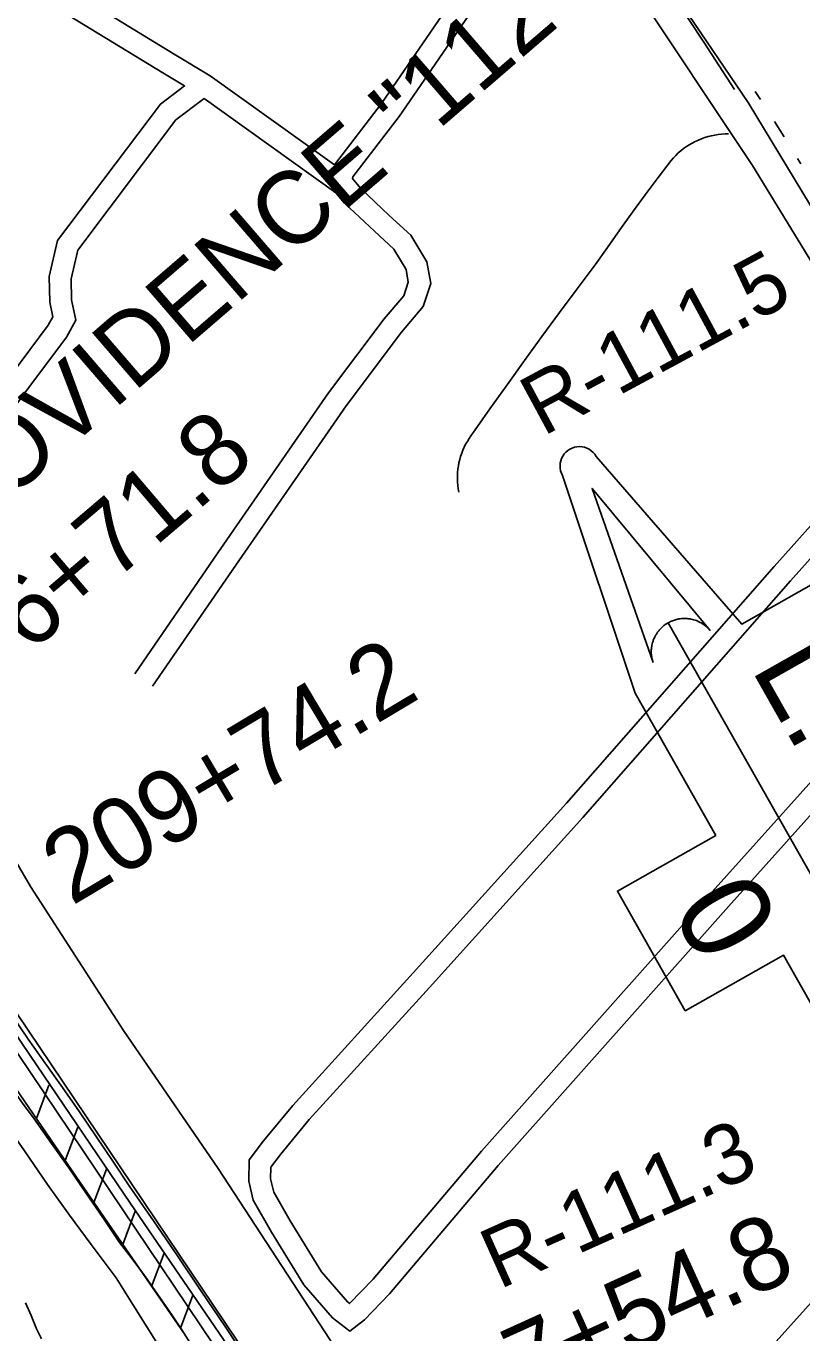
# Model space of a CAD drawing. Extents: x 3625074 to 3663148, y 511451 to 537151.
# Drawn here: x 3632681 to 3633748, y 530470 to 532267 of the extents above; entities that cross this region are included whole.
import ezdxf

# ---------------------------------------------------------------- set-up
doc = ezdxf.new("R2010")
doc.units = 0
for name, color, linetype in [('V-CHAN-NAID', 7, 'Continuous'), ('V-FLOD-BASE', 7, 'Continuous'), ('V-LEVE-TOET', 7, 'Continuous'), ('V-RIVR-RANG-IDEN', 7, 'Continuous'), ('V-ROAD-CNTR', 7, 'Continuous'), ('V-RRAP-FSHR', 7, 'Continuous'), ('V-SITE-VEGE', 7, 'Continuous'), ('V-SURV-IDEN', 7, 'Continuous'), ('V-SURV-LINE', 7, 'Continuous'), ('V-TOPO-SHOR', 7, 'Continuous'), ('V-TOPO-WATR-IDEN', 7, 'Continuous')]:
    doc.layers.add(name, color=color, linetype=linetype)

msp = doc.modelspace()

# ---------------------------------------------------------------- linework, layer by layer
at = {"layer": 'V-FLOD-BASE'}
msp.add_lwpolyline([(3632971.5, 530433.4), (3632824.8, 530647.7), (3632686.6, 530851.6), (3632644.4, 530913.1)], dxfattribs=at)
at = {"layer": 'V-LEVE-TOET'}
for points in [[(3632616.5, 531204.5), (3632687.2, 531083.7), (3632815, 530885.9), (3632945, 530696), (3633098.7, 530460.9), (3633162.2, 530348.5), (3633259.8, 530177.1), (3633278.3, 530140.5)], [(3632556.9, 530960.1), (3632570.4, 530941.6), (3632585, 530919), (3632599.7, 530896.5), (3632614.7, 530874.2), (3632629.8, 530851.9), (3632645.1, 530829.8), (3632660.6, 530807.8), (3632676.3, 530785.9), (3632692.1, 530764.2), (3632716, 530730.5), (3632739.7, 530696.7), (3632763.2, 530662.7), (3632786.5, 530628.6), (3632809.6, 530594.3), (3632822.4, 530577.6), (3632835, 530560.7), (3632847.4, 530543.6), (3632859.6, 530526.5), (3632871.6, 530509.2), (3632883.4, 530491.7), (3632895, 530474.1), (3632906.4, 530456.4)]]:
    msp.add_lwpolyline(points, dxfattribs=at)
at = {"layer": 'V-ROAD-CNTR'}
for points in [[(3630794.8, 534889.3), (3631012.7, 534740.9), (3631533.9, 534398.3), (3632035.9, 534076), (3632223.9, 533952.9), (3632498.3, 533771.5), (3632544.6, 533741.7), (3632585.8, 533709.9), (3632636.4, 533664.9), (3632687.2, 533616.9), (3632771.6, 533500.7), (3632901.2, 533307.7), (3633097.2, 533008), (3633444.7, 532500.1), (3633673.9, 532162.2), (3633780.9, 531985.9)], [(3630772.8, 534841.6), (3630973.5, 534715.2), (3631249.4, 534533.4), (3631423.8, 534418.9), (3631714.9, 534229.7), (3632030.5, 534025.6), (3632185.5, 533923.4), (3632466.7, 533740.1), (3632562.9, 533672.1), (3632638.9, 533602), (3632761.3, 533443.4), (3632883.2, 533254.4), (3632974.7, 533112), (3633067.8, 532968.2), (3633219.4, 532738.8), (3633370, 532525.6), (3633514.4, 532324.7), (3633679.9, 532075.4), (3633970, 531601.1)], [(3633396.7, 532480.7), (3633304.7, 532357.7), (3633169.9, 532160.7), (3633105.1, 532076.3)], [(3633420.8, 532462.7), (3633329.1, 532340.3), (3633194.2, 532143.1), (3633130.4, 532060.1), (3633129.8, 532057.6), (3633140.7, 532044.5), (3633180.5, 532007), (3633210, 531979.6), (3633232.3, 531942.9), (3633237.4, 531913.1), (3633227.1, 531881.5), (3633197.1, 531846.1), (3633121.1, 531745.2), (3632969.4, 531525.8), (3632855.1, 531359.4)], [(3632934.1, 532198.9), (3632884.6, 532228.5), (3632689.5, 532348.3)], [(3632456.5, 531511.4), (3632660.9, 531788.3), (3632711.5, 531855.9), (3632717.8, 531867.5), (3632713.7, 531887.6), (3632713, 531922.8), (3632724.3, 531972.3), (3632865.7, 532160), (3632899, 532185), (3632869, 532202.9), (3632672.1, 532323.7)], [(3633569.7, 532310.1), (3633593.1, 532275.1), (3633612.8, 532245.2), (3633634.2, 532212.6), (3633655.3, 532179.9)], [(3632934.1, 532198.9), (3633105.1, 532076.3)], [(3632480.7, 531493.6), (3632685, 531770.4), (3632736.8, 531839.6), (3632749.4, 531862.8), (3632743.6, 531890.9), (3632743.1, 531919.7), (3632752.1, 531959.3), (3632887.1, 532138.6), (3632926, 532167.8)], [(3632926, 532167.8), (3633107.2, 532037.9)], [(3633646.9, 532119.1), (3633642.2, 532119), (3633637.5, 532118.7), (3633632.8, 532118.2), (3633628.1, 532117.5), (3633623.5, 532116.5), (3633618.9, 532115.4), (3633614.4, 532114), (3633610, 532112.4), (3633605.6, 532110.6), (3633601.3, 532108.6), (3633597.1, 532106.4), (3633593, 532104.1), (3633589.1, 532101.5), (3633585.2, 532098.8), (3633581.5, 532095.8), (3633577.9, 532092.8), (3633574.5, 532089.5), (3633571.2, 532086.1), (3633568.1, 532082.6), (3633550.2, 532058.9), (3633532.5, 532035.1), (3633515, 532011.2), (3633497.6, 531987.2), (3633480.5, 531963), (3633463.5, 531938.8), (3633438.9, 531906.1), (3633414.5, 531873.3), (3633390.3, 531840.4), (3633366.3, 531807.3), (3633342.5, 531774.1), (3633318.8, 531740.7), (3633295.4, 531707.2), (3633292.7, 531703.6), (3633290.1, 531699.9), (3633287.8, 531696.1), (3633285.5, 531692.1), (3633283.5, 531688.1), (3633281.7, 531684), (3633280.1, 531679.7), (3633278.6, 531675.5), (3633277.4, 531671.1), (3633276.3, 531666.7), (3633275.5, 531662.3), (3633274.8, 531657.8), (3633274.4, 531653.3), (3633274.2, 531648.8), (3633274.2, 531644.3), (3633274.4, 531639.8), (3633274.8, 531635.3), (3633275.4, 531630.8), (3633276.3, 531626.4)], [(3633107.2, 532037.9), (3633118.8, 532023.9), (3633160, 531985.1), (3633186.5, 531960.5), (3633203.7, 531932.3), (3633206.6, 531915.3), (3633200.4, 531896.4), (3633173.6, 531864.8), (3633096.7, 531762.7), (3632944.7, 531542.8), (3632830.4, 531376.4)], [(3634039.4, 531495.2), (3633973.8, 531420.7), (3633646.8, 531056.5), (3633330, 530700), (3633180.6, 530523.6), (3633146.2, 530487.9), (3633126.3, 530472.2), (3633102.6, 530490.6), (3633062.9, 530535.8), (3633018.5, 530608.6), (3632993.3, 530652.2), (3632987.2, 530678.6), (3632987.7, 530707.9), (3633007.4, 530733.8), (3633047.7, 530782.8), (3633213.3, 530965.1), (3633424.2, 531198.6), (3633709.7, 531524.1), (3633849.4, 531680.5), (3633888.9, 531725.2)], [(3634016.9, 531515), (3633951.4, 531440.6), (3633624.4, 531076.4), (3633307.4, 530719.7), (3633158.3, 530543.7), (3633125.9, 530510.2), (3633126.1, 530510.3), (3633123.2, 530512.6), (3633087.2, 530553.7), (3633044.3, 530623.9), (3633021.5, 530663.3), (3633017.3, 530681.7), (3633017.6, 530697.6), (3633031, 530715.2), (3633070.4, 530763.2), (3633235.6, 530945), (3633446.6, 531178.7), (3633732.2, 531504.2), (3633871.8, 531660.5), (3633911.4, 531705.3)], [(3634277.2, 531085.3), (3634196.4, 531004.2), (3633969.5, 530745.6), (3633805.6, 530561.8), (3633372.1, 530079)], [(3632632, 530950.1), (3632683.7, 530873.9), (3632707.4, 530840.7)], [(3632707.4, 530840.7), (3632731, 530807.3), (3632754.3, 530773.7), (3632777.4, 530740), (3632800.2, 530706.1), (3632822.9, 530672.2), (3632856.2, 530624), (3632889.2, 530575.7), (3632922, 530527.3), (3632954.6, 530478.6), (3632986.9, 530429.9)]]:
    msp.add_lwpolyline(points, dxfattribs=at)
at = {"layer": 'V-RRAP-FSHR'}
for p, q in [((3632695.2, 530764.7), (3632712.4, 530810.4)), ((3632734.8, 530707), (3632752, 530752.7)), ((3632774.4, 530649.2), (3632791.6, 530695)), ((3632814, 530591.5), (3632831.2, 530637.2)), ((3632853.6, 530533.8), (3632870.8, 530579.5)), ((3632893.2, 530476.1), (3632910.4, 530521.8))]:
    msp.add_line(p, q, dxfattribs=at)
msp.add_lwpolyline([(3631673.9, 532278.1), (3631870.7, 531995.4), (3632026.6, 531760.3), (3632223.6, 531470.9), (3632511.5, 531032.6), (3632750.5, 530684.2), (3632899.2, 530467.4), (3632993.3, 530316.6), (3633085.4, 530131), (3633184.5, 529917.7), (3633256.5, 529764.5), (3633343, 529548.3), (3633478.2, 529185.2), (3633576.4, 528917.5), (3633718.3, 528535.8), (3633831.8, 528240.8)], dxfattribs=at)
at = {"layer": 'V-SITE-VEGE'}
for points in [[(3632517, 530956.9), (3632540.2, 530925.5), (3632570.1, 530883.9), (3632599, 530842.1), (3632661.2, 530746), (3632678.8, 530720.2), (3632710.5, 530674.1), (3632740.6, 530631.9), (3632770.7, 530591.2), (3632804.8, 530545.5), (3632827.9, 530508.8), (3632876.3, 530431.4)], [(3632702.1, 530461.7), (3632695.3, 530475.4), (3632688.1, 530493.7), (3632680.2, 530511.1)]]:
    msp.add_lwpolyline(points, dxfattribs=at)
at = {"layer": 'V-SURV-LINE'}
for points in [[(3632604.3, 531004.1), (3633017.9, 530389.8)], [(3632993, 530373.1), (3632579.5, 530987.4)]]:
    msp.add_lwpolyline(points, dxfattribs=at)
at = {"layer": 'V-TOPO-SHOR'}
for p, q in [((3633690.8, 532166.4), (3633683.7, 532177.5)), ((3633723.3, 532115.1), (3633710.3, 532136)), ((3633746.3, 532078), (3633741.6, 532085.4))]:
    msp.add_line(p, q, dxfattribs=at)
at = {"layer": 'V-TOPO-WATR-IDEN'}
msp.add_line((3633563.9, 531446.6), (3633934.1, 530792.9), dxfattribs=at)
for points in [[(3633464.8, 531675.4), (3633665.2, 531444.8), (3633791.1, 531516.1), (3634105.7, 530960.5), (3633979.8, 530889.2), (3634079.3, 530590.1)], [(3634033.2, 530564), (3633822.7, 530812.4), (3633722.5, 530989.5), (3633587.4, 530912.9), (3633494.2, 531077.5), (3633629.4, 531154), (3633518.6, 531349.6), (3633418.7, 531649.3)]]:
    msp.add_lwpolyline(points, dxfattribs=at)
msp.add_lwpolyline([(3633543.3, 531391.8), (3633459.3, 531631.4), (3633621.6, 531436.1), (3633618.5, 531439.5), (3633615.2, 531442.4), (3633613.8, 531443.5), (3633612.5, 531444.4), (3633610.9, 531445.4), (3633609.4, 531446.4), (3633608, 531447.1), (3633606, 531448.1), (3633603.9, 531449.1), (3633602.7, 531449.5), (3633601.1, 531450.1), (3633599, 531450.8), (3633597.3, 531451.2), (3633595.5, 531451.6), (3633594.3, 531451.8), (3633593, 531452), (3633591.4, 531452.2), (3633589.9, 531452.4), (3633588.4, 531452.5), (3633587.1, 531452.5), (3633585.3, 531452.5), (3633583.6, 531452.4), (3633582.2, 531452.3), (3633580.5, 531452.1), (3633579.1, 531451.9), (3633577.9, 531451.7), (3633576.9, 531451.5), (3633575.4, 531451.1), (3633573.9, 531450.7), (3633572.5, 531450.3), (3633571.1, 531449.8), (3633569.8, 531449.4), (3633568.4, 531448.8), (3633567.3, 531448.3), (3633565.7, 531447.5), (3633563.9, 531446.6), (3633563.4, 531446.2), (3633562.6, 531445.8), (3633561.7, 531445.2), (3633560.8, 531444.6), (3633559.9, 531444), (3633559.1, 531443.4), (3633558.2, 531442.7), (3633557.5, 531442.2), (3633556.6, 531441.4), (3633555.7, 531440.6), (3633555.2, 531440.1), (3633553.7, 531438.7), (3633553, 531437.9), (3633552.5, 531437.4), (3633551.7, 531436.4), (3633551, 531435.6), (3633550.3, 531434.7), (3633549.5, 531433.6), (3633548.7, 531432.6), (3633548.2, 531431.8), (3633547.7, 531431.1), (3633547.1, 531430.1), (3633546.6, 531429.2), (3633546.1, 531428.2), (3633545.5, 531427.1), (3633545, 531426), (3633544.3, 531424.6), (3633543.9, 531423.5), (3633543.5, 531422.4), (3633543.1, 531421.2), (3633542.8, 531420.3), (3633542.5, 531419.3), (3633542.1, 531417.8), (3633542.1, 531417.7), (3633541.9, 531416.8), (3633541.7, 531416.2), (3633541.5, 531415.1), (3633541.3, 531413.9), (3633541.1, 531412.9), (3633541, 531411.9), (3633540.9, 531410.8), (3633540.8, 531409.6), (3633540.8, 531408.8), (3633540.7, 531407.8), (3633540.7, 531406.3), (3633540.8, 531405.4), (3633540.8, 531404.8), (3633540.8, 531404.1), (3633540.9, 531403.4), (3633540.9, 531402.4), (3633541, 531401.4), (3633541.2, 531400.5), (3633541.3, 531399.5), (3633541.5, 531398.3), (3633541.7, 531397.6), (3633541.9, 531396.4), (3633542.3, 531395), (3633542.5, 531394), (3633542.8, 531393.3), (3633543, 531392.6), (3633543.1, 531392.1)], close=True, dxfattribs=at)
msp.add_arc((3633441.8, 531662.4), 26.5, 29.5174, 209.5174, dxfattribs=at)

# ---------------------------------------------------------------- texts
at = {"layer": 'V-CHAN-NAID'}
msp.add_text('PROVIDENCE "112" (111.3)', height=100, rotation=40.7778, dxfattribs=at).set_placement((3632513.7, 531490.8))
at = {"layer": 'V-RIVR-RANG-IDEN'}
for s, rotation, p in [('R-111.5', 28.3828, (3633391.7, 531702.3)), ('R-111.3', 24.1533, (3633331.5, 530529.1))]:
    msp.add_text(s, height=83, rotation=rotation, dxfattribs=at).set_placement(p)
at = {"layer": 'V-SURV-IDEN'}
for s, rotation, p in [('206+71.8', 40.3856, (3632572, 531307)), ('209+74.2', 30.8492, (3632743.7, 531056.6)), ('217+54.8', 24.4711, (3633232.7, 530315.6))]:
    msp.add_text(s, height=100, rotation=rotation, dxfattribs=at).set_placement(p)
at = {"layer": 'V-TOPO-WATR-IDEN'}
for s, rotation, p in [('L.W.R.P.', 299.5173, (3633676.5, 531384.8)), ('0', 299.5174, (3633566.6, 531052.1))]:
    msp.add_text(s, height=124.5, rotation=rotation, dxfattribs=at).set_placement(p)

doc.saveas('drawing.dxf')
